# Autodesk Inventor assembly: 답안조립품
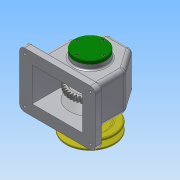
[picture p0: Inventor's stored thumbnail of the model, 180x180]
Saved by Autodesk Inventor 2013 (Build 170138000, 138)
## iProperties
Created: 2016-12
Part Number: 답안조립품
Document SubType Name: Assembly
Designer: Administrator
Author: Administrator
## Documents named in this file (15)
- C:\Users\Administrator\Desktop\461207v1007\답안조립품.iam
- C:\Users\Administrator\Desktop\461207v1007\본체.ipt
- C:\Users\Administrator\Desktop\461207v1007\V-벨트풀리.ipt
- C:\Users\Administrator\Desktop\461207v1007\뒤커버.ipt
- C:\Users\Administrator\Desktop\461207v1007\멈춤나사 - M4x10.ipt
- C:\Users\Administrator\Desktop\461207v1007\베어링 6203.ipt
- C:\Users\Administrator\Desktop\461207v1007\볼트 M3 x 8.ipt
- C:\Users\Administrator\Desktop\461207v1007\볼트 M3 x 10.ipt
- C:\Users\Administrator\Desktop\461207v1007\부시.ipt
- C:\Users\Administrator\Desktop\461207v1007\스퍼기어.ipt
- C:\Users\Administrator\Desktop\461207v1007\앞커버.ipt
- C:\Users\Administrator\Desktop\461207v1007\오일씰 28 40 8.ipt
- C:\Users\Administrator\Desktop\461207v1007\축.ipt
- C:\Users\Administrator\Desktop\461207v1007\키 - 5 x 5 x 18.ipt
- C:\Users\Administrator\Desktop\461207v1007\키 - 6 x 6 x 22.ipt
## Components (9 placed, 3 different names)
1. V-벨트풀리:1
2. ISO 4762 M3 x 8:1
3. ISO 4762 M3 x 8:2
4. ISO 4762 M3 x 8:3
5. ISO 4762 M3 x 8:4
6. ISO 4762 M3 x 10:1
7. ISO 4762 M3 x 10:2
8. ISO 4762 M3 x 10:3
9. ISO 4762 M3 x 10:4
